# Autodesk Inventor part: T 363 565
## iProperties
Created: 2006-04
Part Number: T 363 565
Material: 1.0120.01
Document SubType Name: Sheet Metal
Designer: I.Baliuc
Description: Winkel
Density: 7.84 g/cm^3
Sheet Metal Rule: Default
Title: Winkel
Company: Mayer & Müller AG Schaltgeräte
HalbzeugNorm: DIN 174
Zweck: für LBK - Abdeckung
Abmessung: 14 x 3
Author: T.Messerschmitt
Keywords: 266355
Revision Number: 363565
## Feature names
1. Bohrung1 [Hole]
2. Grobblech1
3. Grobblech2
4. Biegung1
